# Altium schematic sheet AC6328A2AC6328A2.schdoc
size 127 x 101 mm
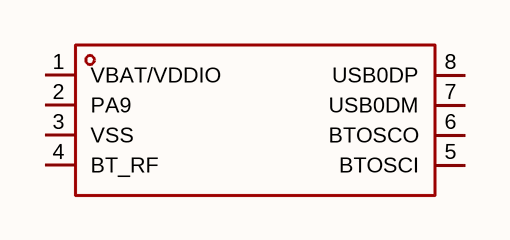
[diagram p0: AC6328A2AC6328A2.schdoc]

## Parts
U?  ac6328a2  [SOP-8_L4.9-W3.9-P1.27-LS6.0-BL]  (value not drawn)

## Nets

Not connected (* = marked no-connect by the designer): U? 1(VBAT/VDDIO) 2(PA9) 3(VSS) 4(BT_RF) 5(BTOSCI) 6(BTOSCO) 7(USB0DM) 8(USB0DP)

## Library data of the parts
U? = ac6328a2: CPU内核:RISC;CPU最大主频:96MHz;CPU位数:32 Bit;; Manufacturer: JL(杰理); AddInBom: yes; ModelId: 75c24a7891ee4dd6bdac16a7163ff87e; ModelName: SOP-8_L4.9-W3.9-P1.27-LS6.0-BL-1; ModelTransform: 192.913,236.22,0,0,0,0,-0.393,2.749,0; CPU Core: RISC; CPU Maximum Speed: 96MHz; Core Size: 32 Bit; Number of I/O: 3; ADC (Bit): 10bit; Voltage - Supply: 1.8V~3.4V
